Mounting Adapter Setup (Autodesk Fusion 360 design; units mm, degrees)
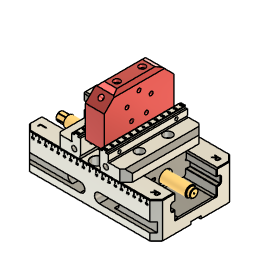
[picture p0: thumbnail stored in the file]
base_feature "Base Feature1"
base_feature "Base Feature1"
base_feature "Base Feature1"
base_feature "Base Feature1"
base_feature "Base Feature1"
as_built_joint "As-built1"
as_built_joint "As-built2"
as_built_joint "As-built3"
as_built_joint "As-built4"
as_built_joint "As-built5" OffsetX 0 OffsetY 0 OffsetZ 0 AngleZ 0
as_built_joint "As-built6" OffsetX 0 OffsetY 0 OffsetZ 0 AngleZ 0
motion_link "MotionLink1" Value1 1 Value2 1
joint_origin "JointOrigin1" OffsetX 0 OffsetY 0 OffsetZ -3 AngleZ 0
sketch "Sketch1" plane through (0, 0, 0) normal (0, 1, 0) x axis (1, 0, 0)
  line L1 (-55, 35) -> (55, 35)
  line L2 (-55, -35) -> (-55, 35)
  line L3 (55, -35) -> (-55, -35)
  line L4 (55, 35) -> (55, -35)
  line L5 (-55, -35) -> (55, 35)
  line L6 (55, -35) -> (-55, 35)
  circle C1 centre (0, 0) radius 20
  circle C2 centre (0, -20) radius 3
  circle C3 centre (19.0211, -6.1803) radius 3
  circle C4 centre (11.7557, 16.1803) radius 3
  circle C5 centre (-11.7557, 16.1803) radius 3
  circle C6 centre (-19.0211, -6.1803) radius 3
  point P6 (0, 0)
  point P1 (0, 0)
  point P7 (0, 0)
  point P8 (0, -20)
  point P4 (-55, -35)
  point P5 (55, -35)
  point P3 (-55, 35)
  horizontal L1
  perpendicular L1 L2
  parallel L1 L3
  parallel L2 L4
  coincident L5 P6
  coincident L6 P6
  coincident P1 P6
  coincident P1 P7
  coincident C1 P8
  vertical P1 P8
  dimension "d1_1" distance P4 P5 = 110
  dimension "d2_1" distance P3 P4 = 70
  dimension "d3_1" diameter C1 = 40
  dimension "d4_1" diameter C2 = 6
  dimension "d6_1" C-Pattern1-Angle = 360
extrude "Extrude1" new body sketch "Sketch1" profile of L1 L2 L3 L4 C2 C3 C4 C5 C6 along normal blind 30 named "d7_1"
chamfer "Chamfer1" distance 20 named "d9_1"
sketch "Sketch2" plane through (-35, 0, 35) normal (-0.7071, 0, 0.7071) x axis (0, -1, 0)
  line L1 (-30, -28.2843) -> (-30, 0)
  line L2 (0, -28.2843) -> (-30, -28.2843)
  line L3 (0, 0) -> (0, -28.2843)
  line L4 (-30, 0) -> (0, 0)
  line L5 (-15, -14.1421) -> (-30, -14.1421)
  line L6 (-15, 0) -> (-15, -14.1421)
  circle C1 centre (-15, -14.1421) radius 4
  point P7 (-30, -14.1421)
  point P6 (-15, -14.1421)
  point P8 (-15, -14.1421)
  point P9 (-15, 0)
  midpoint L1 P7
  coincident P6 P8
  midpoint L4 P9
  perpendicular L4 L6
  horizontal L5
  dimension "d10_1" diameter C1 = 8
extrude "Extrude2" cut sketch "Sketch2" profile of C1 against normal blind 10 named "d11_1"
mirror "Mirror1" mirrorStitchTolerance 0.1 named "d14_1"
sketch "Sketch3" plane through (0, 0, 35) normal (0, 0, 1) x axis (-1, 0, 0)
  line L1 (-35, -30) -> (-35, 0)
  line L2 (35, -30) -> (-35, -30)
  line L3 (35, 0) -> (35, -30)
  line L4 (-35, 0) -> (35, 0)
  line L5 (-35, -15) -> (35, -15)
  line L6 (0, -8.2248) -> (0, -15)
  circle C1 centre (20, -15) radius 5
  circle C2 centre (-20, -15) radius 5
  point P6 (35, -15)
  point P7 (-35, -15)
  point P8 (20, -15)
  point P9 (0, -15)
  midpoint L3 P6
  midpoint L1 P7
  coincident L5 P8
  midpoint L5 P9
  perpendicular L5 L6
  symmetric C1 L6 C2
  dimension "d15" diameter C1 = 10
  dimension "d16" distance P8 L6 = 20
extrude "Extrude3" cut sketch "Sketch3" profile of C1 C2 against normal blind 5
chamfer "Chamfer2" distance 5
ground "Ground1"
position "Position2"
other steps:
create_component "CreateComponent1"
create_component "CreateComponent2"
create_component "CreateComponent3"
create_component "CreateComponent4"
create_component "CreateComponent5"
create_component "CreateComponent1"
create_component "CreateComponent2"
